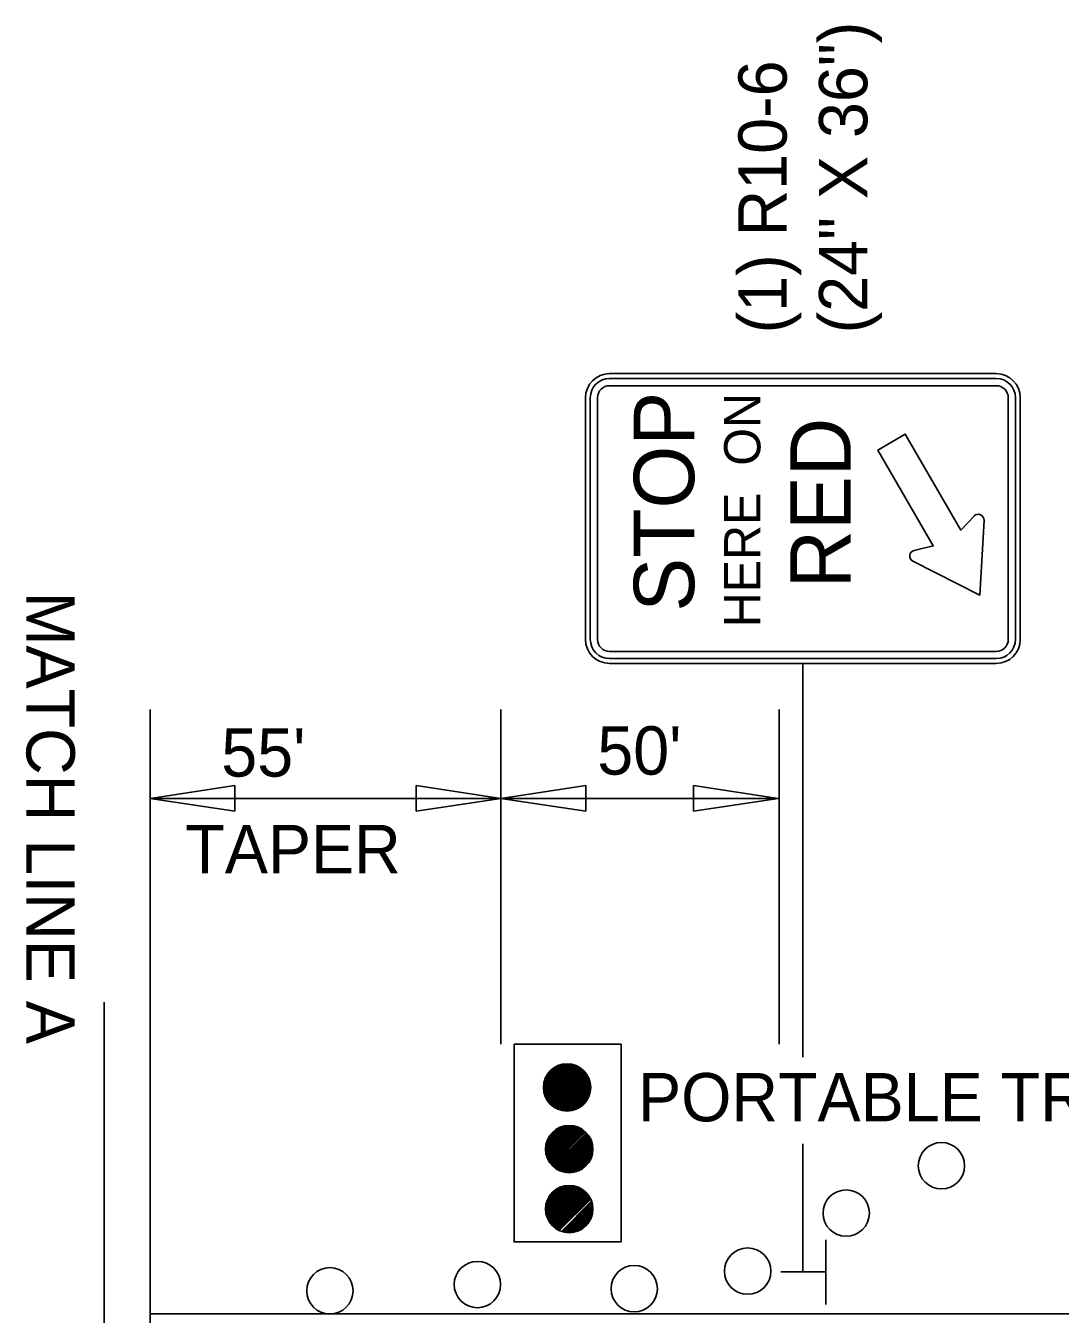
# Model space of a CAD drawing. Extents: x 1930579 to 1934718, y 596452 to 597844.
# Drawn here: x 1932363.4 to 1932491.9, y 596915.3 to 597075.3 of the extents above; entities that cross this region are included whole.
import ezdxf

# ---------------------------------------------------------------- set-up
doc = ezdxf.new("R2010")
doc.units = 0
for name, color, linetype in [('Default', 7, 'Continuous'), ('P_TC_Signs_Permanent', 7, 'Continuous'), ('R_Annotation', 7, 'Continuous')]:
    doc.layers.add(name, color=color, linetype=linetype)

msp = doc.modelspace()

# ---------------------------------------------------------------- linework, layer by layer
at = {"layer": 'Default'}
for p, q in [((1932378.86, 596990.38), (1932378.86, 596879.75)), ((1932422.42, 596990.38), (1932422.42, 596948.8)), ((1932456.99, 596990.38), (1932456.99, 596948.8)), ((1932378.86, 596979.34), (1932389.4, 596980.92)), ((1932389.4, 596980.92), (1932389.4, 596977.76)), ((1932411.88, 596977.76), (1932411.88, 596980.92)), ((1932411.88, 596980.92), (1932422.42, 596979.34)), ((1932422.42, 596979.34), (1932432.96, 596980.92)), ((1932432.96, 596980.92), (1932432.96, 596977.76)), ((1932446.33, 596977.76), (1932446.33, 596980.92)), ((1932446.33, 596980.92), (1932456.87, 596979.34)), ((1932389.4, 596977.76), (1932378.86, 596979.34)), ((1932378.86, 596979.34), (1932422.42, 596979.34)), ((1932422.42, 596979.34), (1932411.88, 596977.76)), ((1932422.42, 596979.34), (1932456.87, 596979.34)), ((1932432.96, 596977.76), (1932422.42, 596979.34)), ((1932456.87, 596979.34), (1932446.33, 596977.76)), ((1932373.16, 596954.05), (1932373.16, 596901.83)), ((1932427.69, 596943.48), (1932430.59, 596946.38)), ((1932427.7, 596943.31), (1932430.77, 596946.38)), ((1932427.7, 596943.67), (1932430.4, 596946.37)), ((1932427.71, 596943.14), (1932430.94, 596946.37)), ((1932427.72, 596943.88), (1932430.2, 596946.35)), ((1932427.73, 596942.98), (1932431.1, 596946.35)), ((1932427.76, 596942.83), (1932431.25, 596946.32)), ((1932427.77, 596944.1), (1932429.97, 596946.31)), ((1932427.79, 596942.68), (1932431.4, 596946.28)), ((1932427.83, 596942.54), (1932431.54, 596946.24)), ((1932427.84, 596944.35), (1932429.72, 596946.24)), ((1932427.88, 596942.41), (1932431.67, 596946.2)), ((1932427.93, 596942.28), (1932431.8, 596946.14)), ((1932427.95, 596944.65), (1932429.43, 596946.13)), ((1932427.99, 596942.15), (1932431.92, 596946.09)), ((1932428.05, 596942.03), (1932432.04, 596946.03)), ((1932428.12, 596941.92), (1932432.16, 596945.96)), ((1932428.17, 596945.04), (1932429.03, 596945.91)), ((1932428.19, 596941.81), (1932432.27, 596945.89)), ((1932428.26, 596941.7), (1932432.37, 596945.81)), ((1932428.34, 596941.6), (1932432.48, 596945.74)), ((1932428.42, 596941.5), (1932432.57, 596945.65)), ((1932428.51, 596941.41), (1932432.67, 596945.57)), ((1932428.6, 596941.32), (1932432.76, 596945.48)), ((1932428.69, 596941.23), (1932432.85, 596945.38)), ((1932428.79, 596941.15), (1932432.93, 596945.28)), ((1932428.89, 596941.07), (1932433.01, 596945.18)), ((1932429, 596941), (1932433.08, 596945.07)), ((1932429.11, 596940.92), (1932433.15, 596944.96)), ((1932429.23, 596940.86), (1932433.22, 596944.85)), ((1932429.35, 596940.8), (1932433.28, 596944.73)), ((1932429.47, 596940.74), (1932433.34, 596944.61)), ((1932429.6, 596940.69), (1932433.39, 596944.48)), ((1932429.73, 596940.64), (1932433.43, 596944.34)), ((1932429.87, 596940.6), (1932433.48, 596944.2)), ((1932430.02, 596940.57), (1932433.51, 596944.06)), ((1932430.17, 596940.54), (1932433.54, 596943.9)), ((1932430.33, 596940.52), (1932433.56, 596943.74)), ((1932430.5, 596940.5), (1932433.57, 596943.58)), ((1932430.68, 596940.5), (1932433.57, 596943.4)), ((1932430.87, 596940.51), (1932433.57, 596943.21)), ((1932431.07, 596940.53), (1932433.54, 596943)), ((1932431.3, 596940.58), (1932433.5, 596942.78)), ((1932431.55, 596940.65), (1932433.43, 596942.53)), ((1932431.84, 596940.76), (1932433.32, 596942.24)), ((1932432.24, 596940.98), (1932433.1, 596941.84)), ((1932427.96, 596935.65), (1932431.04, 596938.72)), ((1932427.96, 596935.83), (1932430.86, 596938.72)), ((1932427.97, 596936.02), (1932430.67, 596938.72)), ((1932427.98, 596935.48), (1932431.21, 596938.71)), ((1932427.99, 596936.22), (1932430.47, 596938.69)), ((1932428, 596935.32), (1932431.37, 596938.69)), ((1932428.03, 596935.17), (1932431.52, 596938.66)), ((1932428.04, 596936.44), (1932430.24, 596938.65)), ((1932428.06, 596935.02), (1932431.66, 596938.62)), ((1932428.1, 596934.88), (1932431.8, 596938.58)), ((1932428.11, 596936.69), (1932429.99, 596938.58)), ((1932428.15, 596934.75), (1932431.94, 596938.54)), ((1932428.2, 596934.62), (1932432.07, 596938.48)), ((1932428.22, 596936.99), (1932429.7, 596938.47)), ((1932428.26, 596934.49), (1932432.19, 596938.43)), ((1932428.32, 596934.38), (1932432.31, 596938.37)), ((1932428.39, 596934.26), (1932432.43, 596938.3)), ((1932428.44, 596937.39), (1932429.3, 596938.25)), ((1932428.46, 596934.15), (1932432.54, 596938.23)), ((1932428.53, 596934.04), (1932432.64, 596938.16)), ((1932428.61, 596933.94), (1932432.75, 596938.08)), ((1932428.69, 596933.84), (1932432.84, 596937.99)), ((1932428.78, 596933.75), (1932432.94, 596937.91)), ((1932428.87, 596933.66), (1932433.03, 596937.82)), ((1932428.96, 596933.57), (1932433.11, 596937.72)), ((1932429.06, 596933.49), (1932433.2, 596937.62)), ((1932429.16, 596933.41), (1932433.28, 596937.52)), ((1932429.27, 596933.34), (1932433.35, 596937.42)), ((1932429.38, 596933.27), (1932433.42, 596937.31)), ((1932429.5, 596933.2), (1932433.49, 596937.19)), ((1932429.62, 596933.14), (1932433.55, 596937.07)), ((1932429.74, 596933.08), (1932433.6, 596936.95)), ((1932429.87, 596933.03), (1932433.66, 596936.82)), ((1932430, 596932.98), (1932433.7, 596936.68)), ((1932430.14, 596932.94), (1932433.74, 596936.54)), ((1932430.29, 596932.91), (1932433.78, 596936.4)), ((1932430.44, 596932.88), (1932433.81, 596936.25)), ((1932430.6, 596932.86), (1932433.83, 596936.09)), ((1932430.77, 596932.84), (1932433.84, 596935.92)), ((1932430.95, 596932.84), (1932433.84, 596935.74)), ((1932431.14, 596932.85), (1932433.84, 596935.55)), ((1932431.34, 596932.87), (1932433.81, 596935.34)), ((1932431.56, 596932.92), (1932433.77, 596935.12)), ((1932431.82, 596932.99), (1932433.7, 596934.87)), ((1932432.11, 596933.1), (1932433.59, 596934.58)), ((1932432.51, 596933.32), (1932433.37, 596934.18)), ((1932427.96, 596928.31), (1932430.94, 596931.29)), ((1932427.96, 596928.49), (1932430.76, 596931.28)), ((1932427.97, 596928.13), (1932431.11, 596931.28)), ((1932427.98, 596928.69), (1932430.56, 596931.27)), ((1932427.99, 596927.97), (1932431.28, 596931.26)), ((1932428.01, 596927.81), (1932431.44, 596931.24)), ((1932428.01, 596928.9), (1932430.34, 596931.23)), ((1932428.04, 596927.66), (1932431.58, 596931.21)), ((1932428.07, 596929.14), (1932430.11, 596931.18)), ((1932428.08, 596927.52), (1932431.73, 596931.17)), ((1932428.12, 596927.38), (1932431.86, 596931.12)), ((1932428.16, 596929.41), (1932429.84, 596931.09)), ((1932428.17, 596927.25), (1932432, 596931.08)), ((1932428.23, 596927.12), (1932432.12, 596931.02)), ((1932428.29, 596927), (1932432.24, 596930.96)), ((1932428.32, 596929.75), (1932429.5, 596930.93)), ((1932428.35, 596926.88), (1932432.36, 596930.9)), ((1932428.42, 596926.77), (1932432.48, 596930.83)), ((1932428.49, 596926.66), (1932432.58, 596930.76)), ((1932428.57, 596926.56), (1932432.69, 596930.68)), ((1932428.65, 596926.46), (1932432.79, 596930.6)), ((1932428.73, 596926.36), (1932432.89, 596930.52)), ((1932428.82, 596926.27), (1932432.98, 596930.43)), ((1932428.91, 596926.18), (1932433.07, 596930.34)), ((1932429.01, 596926.1), (1932433.15, 596930.24)), ((1932429.11, 596926.01), (1932433.23, 596930.14)), ((1932429.21, 596925.94), (1932433.31, 596930.04)), ((1932429.32, 596925.87), (1932433.38, 596929.93)), ((1932429.43, 596925.8), (1932433.45, 596929.82)), ((1932429.55, 596925.73), (1932433.51, 596929.7)), ((1932429.67, 596925.67), (1932433.57, 596929.58)), ((1932429.93, 596925.57), (1932433.68, 596929.32)), ((1932430.06, 596925.52), (1932433.72, 596929.18)), ((1932430.21, 596925.49), (1932433.76, 596929.04)), ((1932430.35, 596925.45), (1932433.79, 596928.89)), ((1932430.51, 596925.43), (1932433.82, 596928.74)), ((1932430.67, 596925.41), (1932433.84, 596928.57)), ((1932430.85, 596925.4), (1932433.84, 596928.4)), ((1932431.03, 596925.41), (1932433.84, 596928.22)), ((1932431.23, 596925.42), (1932433.83, 596928.02)), ((1932431.44, 596925.45), (1932433.8, 596927.81)), ((1932431.67, 596925.5), (1932433.74, 596927.58)), ((1932431.94, 596925.59), (1932433.66, 596927.31)), ((1932432.27, 596925.74), (1932433.51, 596926.98)), ((1932432.84, 596926.13), (1932433.12, 596926.41)), ((1932462.77, 596924.51), (1932462.77, 596916.5)), ((1932462.65, 596920.53), (1932457.18, 596920.53)), ((1932378.86, 596915.33), (1932993.57, 596915.28))]:
    msp.add_line(p, q, dxfattribs=at)
msp.add_lwpolyline([(1932424.06, 596948.8), (1932437.35, 596948.8), (1932437.35, 596924.26), (1932424.06, 596924.26)], close=True, dxfattribs=at)
for centre, radius in [((1932430.63, 596943.44), 2.94), ((1932430.9, 596935.78), 2.94), ((1932477.12, 596933.72), 2.88), ((1932430.9, 596928.34), 2.94), ((1932465.3, 596927.84), 2.88), ((1932453.06, 596920.63), 2.88), ((1932401.19, 596918.18), 2.88), ((1932419.5, 596918.96), 2.88), ((1932438.98, 596918.45), 2.88)]:
    msp.add_circle(centre, radius, dxfattribs=at)
at = {"layer": 'P_TC_Signs_Permanent'}
for p, q in [((1932435.92, 597032.09), (1932483.92, 597032.09)), ((1932435.92, 597031.49), (1932483.92, 597031.49)), ((1932435.92, 597030.59), (1932483.92, 597030.59)), ((1932432.92, 596999.09), (1932432.92, 597029.09)), ((1932433.52, 596999.09), (1932433.52, 597029.09)), ((1932434.42, 596999.09), (1932434.42, 597029.09)), ((1932485.42, 597029.09), (1932485.42, 596999.09)), ((1932486.32, 597029.09), (1932486.32, 596999.09)), ((1932486.92, 597029.09), (1932486.92, 596999.09)), ((1932483.92, 596997.59), (1932435.92, 596997.59)), ((1932483.92, 596996.69), (1932435.92, 596996.69)), ((1932483.92, 596996.09), (1932435.92, 596996.09))]:
    msp.add_line(p, q, dxfattribs=at)
for points in [[(1932481.17, 597014.39), (1932479.52, 597012.65), (1932472.64, 597024.57), (1932469.23, 597022.6), (1932476.11, 597010.68), (1932473.74, 597010.13)], [(1932473.58, 597008.79), (1932481.9, 597004.59), (1932482.41, 597013.86)]]:
    msp.add_lwpolyline(points, dxfattribs=at)
for centre, radius, start, end in [((1932435.92, 597029.09), 3, 90, 180), ((1932435.92, 597029.09), 2.4, 90, 180), ((1932483.92, 597029.09), 3, 360, 90), ((1932483.92, 597029.09), 2.4, 360, 90), ((1932435.92, 597029.09), 1.5, 90, 180), ((1932483.92, 597029.09), 1.5, 360, 90), ((1932481.69, 597013.9), 0.72, 356.857, 136.6377), ((1932473.9, 597009.43), 0.72, 103.0349, 243.2286), ((1932435.92, 596999.09), 3, 180, 270), ((1932435.92, 596999.09), 2.4, 180, 270), ((1932435.92, 596999.09), 1.5, 180, 270), ((1932483.92, 596999.09), 3, 270, 360), ((1932483.92, 596999.09), 2.4, 270, 360), ((1932483.92, 596999.09), 1.5, 270, 360)]:
    msp.add_arc(centre, radius, start, end, dxfattribs=at)
at = {"layer": 'R_Annotation'}
for p, q in [((1932459.92, 596947.19), (1932459.92, 596996.09)), ((1932459.92, 596920.53), (1932459.92, 596936.42))]:
    msp.add_line(p, q, dxfattribs=at)

# ---------------------------------------------------------------- texts
at = {"layer": 'Default'}
for s, height, rotation, p in [('MATCH LINE A', 5.9996, 270, (1932363.51, 597005.01)), ("  55' ", 6, 360, (1932383.24, 596982.04)), ("50'", 6, 360, (1932434.39, 596982.29)), ('TAPER', 6, 360, (1932383.24, 596970.04)), ('PORTABLE TRAFFIC SIGNAL SYSTEM', 6, 360, (1932439.45, 596939.23))]:
    msp.add_text(s, height=height, rotation=rotation, dxfattribs=at).set_placement(p)
at = {"layer": 'P_TC_Signs_Permanent'}
for s, height, p in [('STOP', 7.5, (1932446.42, 597002.52)), ('HERE  ON', 4.5, (1932454.64, 597000.59)), ('RED', 7.5, (1932465.86, 597005.42))]:
    msp.add_text(s, height=height, rotation=90, dxfattribs=at).set_placement(p)
at = {"layer": 'R_Annotation'}
for s, height, p in [('(24" X 36")', 5.9996, (1932467.92, 597037.09)), ('(1) R10-6', 6, (1932457.91, 597037.09))]:
    msp.add_text(s, height=height, rotation=90, dxfattribs=at).set_placement(p)

doc.saveas('drawing.dxf')
